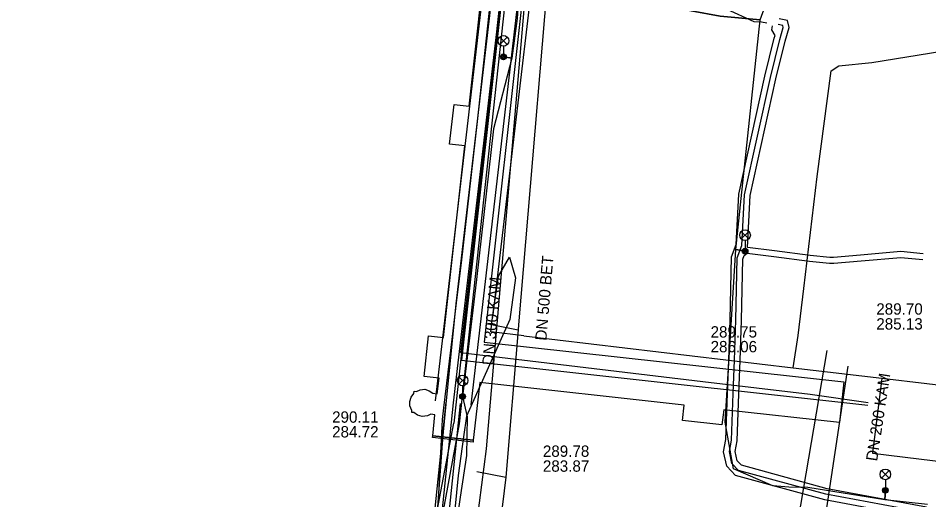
# Model space of a CAD drawing. Extents: x -595540 to -593988, y -1160850 to -1159202.
# Drawn here: x -594539 to -594474.9, y -1160358.3 to -1160324.4 of the extents above; entities that cross this region are included whole.
import ezdxf

# ---------------------------------------------------------------- set-up
doc = ezdxf.new("R2010")
doc.units = 0
for name, color, linetype in [('BVK-DESTOVA_popisy', 7, 'Continuous'), ('BVK-DESTOVA_trasa sítě', 7, 'Continuous'), ('BVK-SPLASKOVA_popisy', 7, 'Continuous'), ('BVK-SPLASKOVA_trasa sítě', 7, 'Continuous'), ('BVK-VODOVOD_trasa sítě', 7, 'Continuous'), ('BVK-VODOVOD_trasa zrušené sítě', 7, 'Continuous'), ('CETIN_kabel podzemní', 7, 'Continuous'), ('DESTOVA_trasa neprovozované sítě', 7, 'Continuous'), ('EON-NN_kabel', 7, 'Continuous'), ('EON-VN_kabel', 7, 'Continuous'), ('QUANTCOM_kabel v kolektoru_kabelovodu', 7, 'Continuous'), ('TEPLARNY-HORKOVODY_trasa sítě', 7, 'Continuous'), ('TEPLARNY-HORKOVODY_trasa sítě obvodem', 7, 'Continuous'), ('TEPLARNY-TEPLOVODY_trasa sítě', 7, 'Continuous'), ('TSB_kabel VO', 7, 'Continuous'), ('TSB_kolektor', 7, 'Continuous'), ('TSB_lampy VO', 7, 'Continuous')]:
    doc.layers.add(name, color=color, linetype=linetype)

msp = doc.modelspace()

# ---------------------------------------------------------------- linework, layer by layer
at = {"layer": 'BVK-DESTOVA_popisy'}
for p, q in [((-594478.553, -1160345.419), (-594478.553, -1160345.419)), ((-594502.042, -1160355.44), (-594502.042, -1160355.44))]:
    msp.add_line(p, q, dxfattribs=at)
at = {"layer": 'BVK-DESTOVA_trasa sítě'}
for p, q in [((-594480.547, -1160348.932), (-594482.06, -1160358.898)), ((-594504.651, -1160356.752), (-594508.377, -1160387.435))]:
    msp.add_line(p, q, dxfattribs=at)
msp.add_lwpolyline([(-594501.111, -1160314.501), (-594503.751, -1160346.011), (-594503.781, -1160346.371), (-594504.651, -1160356.752)], dxfattribs=at)
at = {"layer": 'BVK-SPLASKOVA_popisy'}
for p, q in [((-594490.226, -1160346.107), (-594490.226, -1160346.107)), ((-594516.889, -1160352.11), (-594516.889, -1160352.11))]:
    msp.add_line(p, q, dxfattribs=at)
at = {"layer": 'BVK-SPLASKOVA_trasa sítě'}
for p, q in [((-594502.374, -1160312.046), (-594506.046, -1160354.74)), ((-594482.034, -1160347.812), (-594484.109, -1160359.973)), ((-594506.046, -1160354.74), (-594510.032, -1160385.734))]:
    msp.add_line(p, q, dxfattribs=at)
at = {"layer": 'BVK-VODOVOD_trasa sítě'}
for points in [[(-594509.11, -1160352.69), (-594509.02, -1160351.87), (-594508.4, -1160346.83), (-594508.13, -1160344.45), (-594507.77, -1160341.64), (-594507.21, -1160336.66), (-594506.64, -1160331.69), (-594506.1, -1160326.67), (-594505.43, -1160320.36), (-594505.14, -1160318.06), (-594505.04, -1160317.34), (-594504.95, -1160316.69)], [(-594509.32, -1160356.87), (-594509.25, -1160355.51), (-594509.11, -1160352.69)], [(-594509.39, -1160358.23), (-594509.35, -1160357.53), (-594509.32, -1160356.87)], [(-594508.771, -1160402.588), (-594511.83, -1160402.24), (-594512.89, -1160400.59), (-594510.23, -1160368.35), (-594509.72, -1160362.52), (-594509.39, -1160358.23)]]:
    msp.add_lwpolyline(points, dxfattribs=at)
at = {"layer": 'BVK-VODOVOD_trasa zrušené sítě'}
for points in [[(-594509.05, -1160353.56), (-594508.861, -1160351.6), (-594508.16, -1160344.52), (-594505.33, -1160320.36), (-594505.01, -1160316.88)], [(-594509.39, -1160358.23), (-594509.11, -1160354.38), (-594509.05, -1160353.56)]]:
    msp.add_lwpolyline(points, dxfattribs=at)
at = {"layer": 'CETIN_kabel podzemní'}
for points in [[(-594502.13, -1160316.19), (-594505.58, -1160345.5)], [(-594484.42, -1160349.04), (-594484.05, -1160346.76), (-594483.66, -1160343.45), (-594482.72, -1160335.55), (-594481.74, -1160328.1), (-594481.2, -1160327.76), (-594478.86, -1160327.53), (-594466.54, -1160325.52), (-594458, -1160326.73), (-594452.76, -1160330.16), (-594444.1, -1160335.49), (-594430.62, -1160336.35), (-594416.44, -1160338.08), (-594410.73, -1160338.25), (-594406.57, -1160338.42), (-594404.47, -1160337.96), (-594400.72, -1160336.89), (-594399.54, -1160336.32), (-594397.42, -1160336.27), (-594390.27, -1160337.31), (-594387.49, -1160337.63), (-594386.29, -1160337.57)], [(-594505.58, -1160345.5), (-594505.17, -1160342.57), (-594504.4, -1160341.25), (-594503.98, -1160342.7), (-594504.38, -1160345.63), (-594507.43, -1160352.44)], [(-594478.17, -1160349.78), (-594478.81, -1160355.06), (-594472.3, -1160355.849), (-594470.603, -1160341.85), (-594467.82, -1160342.187)], [(-594503.38, -1160346.78), (-594505.7, -1160346.5), (-594505.58, -1160345.5)], [(-594503.38, -1160346.78), (-594484.42, -1160349.04)], [(-594484.42, -1160349.04), (-594478.17, -1160349.78)], [(-594478.17, -1160349.78), (-594471.82, -1160350.53)], [(-594507.43, -1160352.44), (-594507.63, -1160353.91), (-594508.01, -1160356.63), (-594508.96, -1160366.48), (-594510.4, -1160376.57)]]:
    msp.add_lwpolyline(points, dxfattribs=at)
at = {"layer": 'DESTOVA_trasa neprovozované sítě'}
for p, q in [((-594505.901, -1160345.93), (-594503.781, -1160346.371)), ((-594506.688, -1160356.34), (-594504.651, -1160356.752))]:
    msp.add_line(p, q, dxfattribs=at)
at = {"layer": 'EON-NN_kabel'}
for points in [[(-594486.268, -1160324.749), (-594486.638, -1160324.671), (-594487.161, -1160324.661), (-594489.117, -1160323.765)], [(-594475.036, -1160359.678), (-594482.187, -1160358.341), (-594488.465, -1160356.624), (-594489.091, -1160355.983), (-594489.306, -1160354.954), (-594489.15, -1160354.096), (-594489.033, -1160350.841), (-594488.949, -1160348.497), (-594488.847, -1160345.666), (-594488.747, -1160341.224), (-594488.419, -1160340.343), (-594488.237, -1160336.792), (-594486.399, -1160328.486), (-594485.738, -1160325.804), (-594485.682, -1160325.611), (-594485.908, -1160325.215), (-594485.86, -1160324.93)], [(-594475.031, -1160359.272), (-594482.097, -1160357.951), (-594488.255, -1160356.267), (-594488.723, -1160355.787), (-594488.898, -1160354.949), (-594488.751, -1160354.139), (-594488.633, -1160350.855), (-594488.549, -1160348.511), (-594488.447, -1160345.678), (-594488.349, -1160341.3), (-594488.023, -1160340.425), (-594487.839, -1160336.846), (-594486.009, -1160328.577), (-594485.352, -1160325.908), (-594485.103, -1160325.055), (-594485.14, -1160324.904), (-594485.468, -1160324.835)], [(-594475.241, -1160341.015), (-594476.826, -1160340.853), (-594479.659, -1160341.11), (-594481.574, -1160341.275), (-594481.834, -1160341.275), (-594483.206, -1160341.115), (-594485.729, -1160340.798), (-594487.629, -1160340.551), (-594487.441, -1160336.9), (-594485.619, -1160328.668), (-594484.966, -1160326.012), (-594484.689, -1160325.064), (-594484.812, -1160324.564), (-594485.386, -1160324.444)], [(-594475.026, -1160358.867), (-594482.007, -1160357.561), (-594488.045, -1160355.91), (-594488.355, -1160355.591), (-594488.49, -1160354.944), (-594488.352, -1160354.182), (-594488.233, -1160350.869), (-594488.149, -1160348.525), (-594488.047, -1160345.69), (-594487.951, -1160341.376), (-594487.854, -1160341.115), (-594487.641, -1160340.952), (-594485.779, -1160341.194), (-594483.254, -1160341.513), (-594481.858, -1160341.675), (-594481.556, -1160341.675), (-594479.623, -1160341.508), (-594476.828, -1160341.255), (-594475.281, -1160341.413)]]:
    msp.add_lwpolyline(points, dxfattribs=at)
at = {"layer": 'EON-VN_kabel'}
for points in [[(-594507.908, -1160352.983), (-594493.4, -1160219.322), (-594493.357, -1160218.925), (-594485.737, -1160148.725), (-594481.531, -1160104.454), (-594481.385, -1160102.826), (-594480.679, -1160095.006), (-594479.672, -1160088.145), (-594478.228, -1160073.321), (-594478.064, -1160071.488), (-594477.548, -1160064.204), (-594476.903, -1160059.951), (-594476.168, -1160052.428), (-594474.681, -1160037.844), (-594473.216, -1160021.563), (-594473.18, -1160021.165), (-594471.953, -1160007.533), (-594471.871, -1160006.857), (-594471.823, -1160006.461), (-594471.776, -1160006.071), (-594472.104, -1160006.031), (-594491.892, -1160003.645), (-594490.259, -1159978.956)], [(-594486.056, -1160148.673), (-594493.705, -1160218.887), (-594493.748, -1160219.284), (-594508.308, -1160352.93)], [(-594512.55, -1160404.43), (-594512.561, -1160403.767), (-594513.245, -1160402.502), (-594513.563, -1160401.844), (-594513.789, -1160401.425), (-594513.72, -1160398.775), (-594512.759, -1160389.517), (-594511.814, -1160378.396), (-594511.09, -1160370.284), (-594510.545, -1160364.848), (-594509.314, -1160358.256), (-594508.308, -1160352.93)], [(-594493.408, -1160401.037), (-594493.774, -1160403.505), (-594493.944, -1160404.397), (-594494.023, -1160404.739), (-594494.148, -1160404.82), (-594494.767, -1160404.983), (-594495.443, -1160404.99), (-594498.143, -1160404.744), (-594504.051, -1160404.136), (-594510.328, -1160403.578), (-594512.254, -1160402.746), (-594512.85, -1160402.223), (-594513.095, -1160401.769), (-594513.368, -1160401.285), (-594513.229, -1160398.643), (-594512.315, -1160389.542), (-594511.399, -1160378.471), (-594510.528, -1160368.834), (-594510.142, -1160365.02), (-594508.851, -1160358.091), (-594507.908, -1160352.983)]]:
    msp.add_lwpolyline(points, dxfattribs=at)
at = {"layer": 'QUANTCOM_kabel v kolektoru_kabelovodu'}
msp.add_lwpolyline([(-594497.8, -1160258.697), (-594507.764, -1160348.495), (-594479.142, -1160351.669)], dxfattribs=at)
at = {"layer": 'TEPLARNY-HORKOVODY_trasa sítě'}
msp.add_line((-594504.155, -1160315.403), (-594508.356, -1160351.505), dxfattribs=at)
msp.add_lwpolyline([(-594508.356, -1160351.505), (-594511.277, -1160379.614), (-594538.013, -1160376.903), (-594538.776, -1160376.524)], dxfattribs=at)
at = {"layer": 'TEPLARNY-HORKOVODY_trasa sítě obvodem'}
for p, q in [((-594509.597, -1160351.361), (-594505.396, -1160315.258)), ((-594502.913, -1160315.547), (-594507.114, -1160351.65))]:
    msp.add_line(p, q, dxfattribs=at)
for points in [[(-594539.002, -1160375.853), (-594537.872, -1160376.415), (-594511.723, -1160379.066), (-594508.853, -1160351.453)], [(-594507.858, -1160351.557), (-594510.831, -1160380.161), (-594538.624, -1160377.344)]]:
    msp.add_lwpolyline(points, dxfattribs=at)
at = {"layer": 'TEPLARNY-TEPLOVODY_trasa sítě'}
msp.add_line((-594483.213, -1160350.901), (-594479.123, -1160351.484), dxfattribs=at)
msp.add_lwpolyline([(-594504.061, -1160315.407), (-594506.297, -1160334.588), (-594507.856, -1160347.964), (-594490.771, -1160350), (-594483.213, -1160350.901)], dxfattribs=at)
at = {"layer": 'TSB_kabel VO'}
for points in [[(-594505.239, -1160320.305), (-594504.78, -1160320.38), (-594503.646, -1160321.344), (-594496.566, -1160321.991), (-594496.491, -1160323.072), (-594495.676, -1160323.1), (-594489.541, -1160324.25), (-594486.738, -1160324.515), (-594485.761, -1160321.864), (-594482.876, -1160319.267), (-594477.618, -1160318.31), (-594476.538, -1160319.246), (-594475.733, -1160318.696), (-594448.99, -1160321.769), (-594423.733, -1160324.263), (-594413.793, -1160325.724), (-594410.466, -1160326.608), (-594410.38, -1160332.22), (-594406.852, -1160332.549), (-594405.18, -1160332.399), (-594405.258, -1160332.9)], [(-594505.239, -1160320.305), (-594504.78, -1160320.38), (-594503.646, -1160321.344), (-594503.85, -1160324.431), (-594504.226, -1160327.223), (-594504.82, -1160327.124), (-594504.226, -1160327.223), (-594505.52, -1160332.203), (-594506.719, -1160342.814), (-594507.698, -1160351.064), (-594507.363, -1160352.504), (-594507.415, -1160355.214), (-594507.873, -1160358.156), (-594510.406, -1160376.216), (-594510.075, -1160376.681), (-594511.372, -1160385.904), (-594512.208, -1160398.733), (-594512.511, -1160401.619), (-594513.094, -1160402.772)], [(-594474.943, -1160358.678), (-594477.944, -1160358.337), (-594477.916, -1160357.675), (-594477.944, -1160358.337), (-594483.365, -1160357.472), (-594484.713, -1160357.441), (-594485.847, -1160357.36), (-594488.601, -1160356.15), (-594489.198, -1160352.879), (-594488.452, -1160340.697), (-594487.798, -1160340.812), (-594488.452, -1160340.697), (-594488.066, -1160337.102), (-594486.738, -1160324.515), (-594489.541, -1160324.25), (-594495.676, -1160323.1), (-594496.491, -1160323.072), (-594496.566, -1160321.991), (-594503.646, -1160321.344), (-594504.78, -1160320.38), (-594505.239, -1160320.305)]]:
    msp.add_lwpolyline(points, dxfattribs=at)
at = {"layer": 'TSB_kolektor'}
msp.add_lwpolyline([(-594503.386, -1160322.078), (-594506.175, -1160347.223), (-594480.835, -1160350.033), (-594481.152, -1160352.895), (-594489.304, -1160351.991), (-594489.424, -1160353.066), (-594492.207, -1160352.754), (-594492.087, -1160351.683), (-594506.492, -1160350.085), (-594506.942, -1160354.14), (-594509.804, -1160353.823), (-594509.642, -1160352.361), (-594509.925, -1160352.316), (-594510.167, -1160352.436), (-594510.548, -1160352.474), (-594510.882, -1160352.371), (-594511.124, -1160352.195), (-594511.282, -1160352.179), (-594511.263, -1160352.056), (-594511.412, -1160351.721), (-594511.412, -1160351.415), (-594511.319, -1160351.108), (-594511.133, -1160350.857), (-594511.116, -1160350.688), (-594510.938, -1160350.699), (-594510.696, -1160350.597), (-594510.362, -1160350.551), (-594510.046, -1160350.653), (-594509.795, -1160350.83), (-594509.477, -1160350.871), (-594509.354, -1160349.767), (-594510.408, -1160349.65), (-594510.09, -1160346.787), (-594509.037, -1160346.905), (-594507.538, -1160333.387), (-594508.612, -1160333.266), (-594508.301, -1160330.484), (-594507.229, -1160330.604), (-594505.862, -1160318.281)], dxfattribs=at)
msp.add_lwpolyline([(-594506.942, -1160354.14), (-594506.946, -1160354.283), (-594509.809, -1160353.947), (-594509.804, -1160353.823)], close=True, dxfattribs=at)
at = {"layer": 'TSB_lampy VO'}
for p, q in [((-594505.085, -1160326.264), (-594504.555, -1160325.734)), ((-594505.085, -1160325.734), (-594504.555, -1160326.264)), ((-594505.085, -1160326.264), (-594504.555, -1160325.734)), ((-594505.085, -1160325.734), (-594504.555, -1160326.264)), ((-594504.82, -1160326.374), (-594504.82, -1160327.124)), ((-594504.82, -1160326.374), (-594504.82, -1160327.124)), ((-594488.063, -1160339.952), (-594487.533, -1160339.422)), ((-594488.063, -1160339.422), (-594487.533, -1160339.952)), ((-594488.063, -1160339.952), (-594487.533, -1160339.422)), ((-594488.063, -1160339.422), (-594487.533, -1160339.952)), ((-594487.798, -1160340.062), (-594487.798, -1160340.812)), ((-594487.798, -1160340.062), (-594487.798, -1160340.812)), ((-594507.963, -1160350.204), (-594507.433, -1160349.674)), ((-594507.963, -1160349.674), (-594507.433, -1160350.204)), ((-594507.963, -1160350.204), (-594507.433, -1160349.674)), ((-594507.963, -1160349.674), (-594507.433, -1160350.204)), ((-594507.698, -1160350.314), (-594507.698, -1160351.064)), ((-594507.698, -1160350.314), (-594507.698, -1160351.064)), ((-594478.181, -1160356.815), (-594477.651, -1160356.285)), ((-594478.181, -1160356.285), (-594477.651, -1160356.815)), ((-594478.181, -1160356.815), (-594477.651, -1160356.285)), ((-594478.181, -1160356.285), (-594477.651, -1160356.815)), ((-594477.916, -1160356.925), (-594477.916, -1160357.675)), ((-594477.916, -1160356.925), (-594477.916, -1160357.675))]:
    msp.add_line(p, q, dxfattribs=at)
for centre, radius in [((-594504.82, -1160325.999), 0.375), ((-594504.82, -1160325.999), 0.375), ((-594504.82, -1160327.124), 0.2), ((-594504.82, -1160327.124), 0.2), ((-594504.82, -1160327.124), 0.145), ((-594504.82, -1160327.124), 0.145), ((-594504.82, -1160327.124), 0.0876), ((-594504.82, -1160327.124), 0.0876), ((-594487.798, -1160339.687), 0.375), ((-594487.798, -1160339.687), 0.375), ((-594487.798, -1160340.812), 0.2), ((-594487.798, -1160340.812), 0.2), ((-594487.798, -1160340.812), 0.145), ((-594487.798, -1160340.812), 0.145), ((-594487.798, -1160340.812), 0.0876), ((-594487.798, -1160340.812), 0.0876), ((-594507.698, -1160349.939), 0.375), ((-594507.698, -1160349.939), 0.375), ((-594507.698, -1160351.064), 0.2), ((-594507.698, -1160351.064), 0.2), ((-594507.698, -1160351.064), 0.145), ((-594507.698, -1160351.064), 0.145), ((-594507.698, -1160351.064), 0.0876), ((-594507.698, -1160351.064), 0.0876), ((-594477.916, -1160356.55), 0.375), ((-594477.916, -1160356.55), 0.375), ((-594477.916, -1160357.675), 0.2), ((-594477.916, -1160357.675), 0.2), ((-594477.916, -1160357.675), 0.145), ((-594477.916, -1160357.675), 0.145), ((-594477.916, -1160357.675), 0.0876), ((-594477.916, -1160357.675), 0.0876)]:
    msp.add_circle(centre, radius, dxfattribs=at)

# ---------------------------------------------------------------- texts
at = {"layer": 'BVK-DESTOVA_popisy'}
for s, rotation, p in [('DN 500 BET', 85.19882, (-594501.792, -1160347.151)), ('DN 200 KAM', 81.36749, (-594478.498, -1160355.658))]:
    msp.add_text(s, height=0.8, rotation=rotation, dxfattribs=at).set_placement(p)
for s, p in [('289.70', (-594478.553, -1160345.294)), ('285.13', (-594478.553, -1160346.344)), ('289.78', (-594502.042, -1160355.315)), ('283.87', (-594502.042, -1160356.365))]:
    msp.add_text(s, height=0.8, dxfattribs=at).set_placement(p)
at = {"layer": 'BVK-SPLASKOVA_popisy'}
msp.add_text('DN 300 KAM', height=0.8, rotation=85.08423, dxfattribs=at).set_placement((-594505.526, -1160348.888))
for s, p in [('289.75', (-594490.226, -1160346.907)), ('286.06', (-594490.226, -1160347.947)), ('290.11', (-594516.889, -1160352.91)), ('284.72', (-594516.889, -1160353.95))]:
    msp.add_text(s, height=0.8, dxfattribs=at).set_placement(p)

doc.saveas('drawing.dxf')
